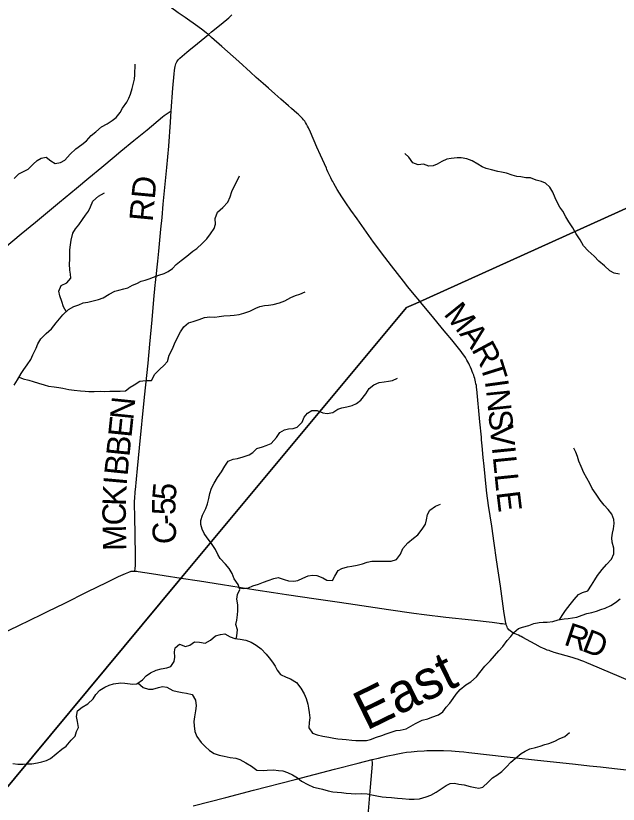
# Model space of a CAD drawing. Extents: x 1442749 to 1756758, y 235267 to 677782.
# Drawn here: x 1584563 to 1592266, y 484946 to 495025 of the extents above; entities that cross this region are included whole.
import ezdxf

# ---------------------------------------------------------------- set-up
doc = ezdxf.new("R2010")
doc.units = 0
for name, color, linetype in [('GM_X_County_Road', 7, 'Continuous'), ('GM_X_County_Road_Text', 7, 'Continuous'), ('GM_X_Minor_River', 7, 'Continuous'), ('GM_X_Minor_River_Text', 7, 'Continuous'), ('GM_X_State_Route', 7, 'Continuous'), ('GM_X_Township', 7, 'Continuous'), ('GM_X_Township_Road', 7, 'Continuous')]:
    doc.layers.add(name, color=color, linetype=linetype)

msp = doc.modelspace()

# ---------------------------------------------------------------- linework, layer by layer
at = {"layer": 'GM_X_County_Road'}
for points in [[(1587025, 494785), (1587002, 494804), (1586955, 494841), (1586889, 494889), (1586728, 495002), (1586640, 495064), (1586424, 495219), (1585934, 495567), (1585838, 495636), (1585718, 495722), (1585571, 495826), (1585546, 495843), (1585522, 495859), (1585489, 495879), (1585469, 495890), (1585449, 495901), (1585419, 495916), (1585390, 495931), (1585249, 495999), (1584874, 496173), (1584761, 496227), (1584597, 496302), (1584467, 496364)], [(1587025, 494785), (1587065, 494818), (1587188, 494917), (1587287, 494998), (1587301, 495011), (1587314, 495023), (1587324, 495035)], [(1586551, 493810), (1586572, 494098), (1586587, 494281), (1586591, 494327), (1586595, 494356), (1586599, 494376), (1586603, 494393), (1586610, 494411), (1586617, 494426), (1586624, 494437), (1586632, 494450), (1586640, 494460), (1586649, 494471), (1586662, 494484), (1586689, 494508), (1586749, 494558), (1586777, 494580), (1586886, 494670), (1587025, 494785)], [(1589707, 491401), (1589680, 491435), (1589578, 491559), (1589519, 491634), (1589365, 491830), (1589281, 491940), (1589138, 492132), (1588926, 492428), (1588846, 492540), (1588782, 492632), (1588732, 492709), (1588673, 492804), (1588628, 492881), (1588615, 492905), (1588605, 492924), (1588590, 492954), (1588579, 492977), (1588565, 493006), (1588554, 493032), (1588542, 493058), (1588534, 493076), (1588461, 493241), (1588413, 493345), (1588331, 493535), (1588305, 493592), (1588293, 493614), (1588281, 493638), (1588268, 493659), (1588257, 493676), (1588242, 493694), (1588228, 493711), (1588211, 493728), (1588196, 493744), (1588176, 493763), (1588156, 493782), (1588089, 493840), (1588052, 493873), (1587954, 493959), (1587877, 494027), (1587794, 494101), (1587724, 494161), (1587638, 494237), (1587564, 494302), (1587414, 494439), (1587196, 494634), (1587066, 494749), (1587025, 494785)], [(1586087, 487927), (1586090, 487960), (1586093, 487996), (1586094, 488019), (1586094, 488039), (1586093, 488131), (1586084, 488633), (1586081, 488767), (1586082, 488797), (1586082, 488826), (1586084, 488854), (1586085, 488878), (1586088, 488914), (1586090, 488942), (1586092, 488966), (1586119, 489237), (1586145, 489502), (1586210, 490151), (1586256, 490585), (1586278, 490826), (1586306, 491137), (1586329, 491398), (1586347, 491580), (1586350, 491616), (1586354, 491652), (1586381, 491890), (1586394, 492017), (1586419, 492295), (1586433, 492445), (1586449, 492615), (1586466, 492787), (1586494, 493085), (1586518, 493359), (1586540, 493663), (1586551, 493810)], [(1590833, 487249), (1590830, 487261), (1590822, 487306), (1590804, 487413), (1590759, 487732), (1590711, 488069), (1590681, 488284), (1590648, 488500), (1590608, 488763), (1590587, 488922), (1590578, 489004), (1590552, 489268), (1590541, 489379), (1590526, 489529), (1590519, 489606), (1590516, 489639), (1590496, 489836), (1590458, 490251), (1590455, 490274), (1590452, 490297), (1590447, 490321), (1590442, 490345), (1590436, 490367), (1590431, 490389), (1590424, 490410), (1590418, 490429), (1590408, 490457), (1590400, 490478), (1590390, 490503), (1590377, 490532), (1590366, 490557), (1590355, 490580), (1590343, 490602), (1590332, 490623), (1590312, 490656), (1590292, 490686), (1590276, 490707), (1590257, 490732), (1590240, 490754), (1590222, 490777), (1590137, 490881), (1590065, 490967), (1590018, 491025), (1589891, 491179), (1589761, 491337), (1589707, 491401)], [(1584039, 486968), (1584145, 487016), (1584338, 487106), (1584584, 487224), (1584761, 487309), (1584882, 487368), (1584979, 487416), (1585180, 487513), (1585486, 487664), (1585722, 487779), (1585878, 487856), (1585964, 487896), (1586007, 487914), (1586018, 487918), (1586029, 487921), (1586039, 487924), (1586052, 487926), (1586069, 487927), (1586087, 487927)], [(1586087, 487927), (1586099, 487926), (1586112, 487925), (1586127, 487923), (1586300, 487895), (1586459, 487869), (1586676, 487837)], [(1586676, 487837), (1586913, 487800), (1587205, 487754), (1587633, 487688), (1587860, 487654), (1588025, 487628), (1588404, 487571), (1588583, 487546), (1588703, 487529), (1588901, 487500), (1589330, 487436), (1589654, 487389), (1589784, 487373), (1590060, 487339), (1590390, 487302), (1590654, 487272), (1590742, 487261), (1590763, 487258), (1590786, 487255), (1590833, 487249)], [(1592417, 486521), (1591916, 486734), (1591865, 486755), (1591828, 486770), (1591786, 486785), (1591757, 486796), (1591717, 486808), (1591676, 486821), (1591446, 486887), (1591424, 486894), (1591402, 486902), (1591382, 486909), (1591359, 486917), (1591333, 486928), (1591304, 486940), (1591282, 486951), (1591257, 486963), (1591251, 486966), (1591150, 487021), (1591047, 487077), (1591027, 487088), (1591012, 487095), (1590991, 487105), (1590970, 487114), (1590948, 487123), (1590934, 487130), (1590920, 487137), (1590900, 487149), (1590884, 487161), (1590869, 487174), (1590858, 487187), (1590851, 487198), (1590844, 487213), (1590840, 487222), (1590837, 487232), (1590834, 487246), (1590833, 487249)]]:
    msp.add_lwpolyline(points, dxfattribs=at)
at = {"layer": 'GM_X_Minor_River'}
for points in [[(1584541, 492943), (1584602, 493003), (1584653, 493030), (1584721, 493063), (1584784, 493126), (1584835, 493174), (1584887, 493203), (1584950, 493216), (1585011, 493172), (1585067, 493137), (1585135, 493148), (1585190, 493179), (1585257, 493255), (1585330, 493326), (1585407, 493379), (1585468, 493428), (1585525, 493494), (1585586, 493543), (1585657, 493604), (1585730, 493645), (1585796, 493687), (1585847, 493726), (1585896, 493789), (1585927, 493843), (1585982, 493919), (1586009, 493970), (1586028, 494024), (1586049, 494094), (1586066, 494162), (1586082, 494214), (1586087, 494268), (1586089, 494408)], [(1592284, 491721), (1592214, 491733), (1592160, 491764), (1592089, 491827), (1592019, 491886), (1591960, 491953), (1591883, 492018), (1591824, 492085), (1591780, 492160), (1591727, 492237), (1591686, 492314), (1591633, 492390), (1591598, 492455), (1591559, 492528), (1591521, 492578), (1591488, 492635), (1591461, 492697), (1591432, 492772), (1591392, 492832), (1591337, 492883), (1591285, 492908), (1591217, 492925), (1591145, 492952), (1591083, 492955), (1591021, 492964), (1590969, 492972), (1590909, 492989), (1590839, 493014), (1590775, 493027), (1590725, 493036), (1590645, 493055), (1590579, 493071), (1590527, 493094), (1590472, 493127), (1590398, 493170), (1590330, 493197), (1590256, 493208), (1590206, 493209), (1590128, 493200), (1590074, 493190), (1590009, 493161), (1589952, 493126), (1589900, 493108), (1589846, 493103), (1589776, 493128), (1589708, 493121), (1589640, 493146), (1589589, 493217), (1589537, 493263)], [(1585682, 491421), (1585755, 491466), (1585829, 491503), (1585880, 491517), (1585944, 491536), (1585994, 491547), (1586057, 491581), (1586111, 491604), (1586166, 491633), (1586216, 491647), (1586269, 491662), (1586323, 491685), (1586390, 491707), (1586460, 491730), (1586511, 491757), (1586565, 491795), (1586614, 491846), (1586677, 491897), (1586750, 491951), (1586825, 492016), (1586877, 492051), (1586946, 492112), (1587007, 492172), (1587054, 492237), (1587099, 492305), (1587116, 492359), (1587113, 492433), (1587142, 492513), (1587209, 492572), (1587276, 492641), (1587303, 492709), (1587326, 492777), (1587357, 492841), (1587390, 492906), (1587425, 492978)], [(1585208, 491243), (1585173, 491306), (1585150, 491372), (1585127, 491444), (1585115, 491503), (1585142, 491578), (1585215, 491610), (1585268, 491671), (1585263, 491723), (1585253, 491775), (1585248, 491852), (1585253, 491910), (1585254, 491980), (1585253, 492032), (1585264, 492096), (1585273, 492158), (1585292, 492246), (1585327, 492302), (1585369, 492353), (1585418, 492419), (1585455, 492474), (1585494, 492528), (1585517, 492584), (1585548, 492654), (1585621, 492721), (1585698, 492762)], [(1584605, 490407), (1584659, 490382), (1584729, 490367), (1584783, 490350), (1584855, 490330), (1584927, 490307), (1584983, 490290), (1585053, 490281), (1585113, 490272), (1585163, 490265), (1585243, 490248), (1585309, 490237), (1585391, 490230), (1585449, 490226), (1585499, 490223), (1585563, 490220), (1585642, 490225), (1585696, 490224), (1585766, 490228), (1585898, 490226), (1585967, 490231), (1586027, 490278), (1586078, 490308), (1586147, 490355), (1586225, 490362), (1586297, 490363), (1586342, 490443), (1586403, 490506), (1586456, 490553), (1586501, 490605), (1586526, 490687), (1586567, 490768), (1586594, 490830), (1586627, 490904), (1586667, 490984), (1586710, 491047), (1586772, 491098), (1586831, 491116), (1586909, 491141), (1586976, 491166), (1587046, 491177), (1587110, 491174), (1587163, 491182), (1587225, 491189), (1587305, 491194), (1587357, 491199), (1587420, 491208), (1587480, 491222), (1587555, 491249), (1587631, 491286), (1587682, 491307), (1587744, 491320), (1587796, 491326), (1587853, 491335), (1587933, 491356), (1588002, 491381), (1588078, 491422), (1588141, 491449), (1588195, 491467), (1588264, 491496)], [(1584540, 490302), (1584585, 490373), (1584632, 490451), (1584667, 490504), (1584710, 490564), (1584755, 490629), (1584781, 490689), (1584823, 490777), (1584846, 490831), (1584884, 490894), (1584952, 490964), (1585019, 491025), (1585078, 491100), (1585123, 491152), (1585165, 491203), (1585236, 491269), (1585305, 491310), (1585368, 491331), (1585426, 491356), (1585484, 491366), (1585551, 491379), (1585621, 491398), (1585682, 491421)], [(1587382, 487062), (1587391, 487100), (1587400, 487174), (1587378, 487244), (1587391, 487300), (1587400, 487368), (1587403, 487418), (1587404, 487496), (1587389, 487569), (1587400, 487625), (1587427, 487691), (1587405, 487755), (1587356, 487826), (1587329, 487896), (1587290, 487961), (1587244, 488014), (1587177, 488087), (1587148, 488137), (1587115, 488202), (1587067, 488281), (1587010, 488353), (1586973, 488408), (1586944, 488461), (1586930, 488521), (1586931, 488571), (1586952, 488639), (1586991, 488726), (1587014, 488786), (1587031, 488856), (1587046, 488916), (1587067, 488986), (1587098, 489052), (1587141, 489123), (1587194, 489195), (1587237, 489266), (1587278, 489330), (1587343, 489359), (1587399, 489367), (1587471, 489386), (1587546, 489413), (1587596, 489442), (1587647, 489492), (1587716, 489513), (1587766, 489530), (1587827, 489559), (1587896, 489633), (1587939, 489696), (1587997, 489732), (1588052, 489743), (1588110, 489750), (1588160, 489764), (1588223, 489831), (1588252, 489895), (1588293, 489946), (1588350, 489978), (1588418, 489977), (1588490, 489950), (1588544, 489939), (1588618, 489952), (1588681, 489997), (1588731, 490013), (1588798, 490026), (1588864, 490043), (1588920, 490068), (1588977, 490110), (1589038, 490193), (1589080, 490261), (1589142, 490306), (1589211, 490337), (1589273, 490346), (1589327, 490352), (1589378, 490361), (1589444, 490392)], [(1591514, 487304), (1591549, 487357), (1591594, 487422), (1591652, 487500), (1591701, 487565), (1591758, 487625), (1591808, 487654), (1591879, 487675), (1591924, 487747), (1591967, 487816), (1592002, 487870), (1592059, 487945), (1592116, 488011), (1592181, 488078), (1592212, 488148), (1592209, 488220), (1592188, 488296), (1592186, 488351), (1592195, 488409), (1592204, 488465), (1592213, 488533), (1592208, 488585), (1592185, 488653), (1592137, 488714), (1592086, 488767), (1592036, 488832), (1591983, 488908), (1591934, 488983), (1591905, 489046), (1591864, 489112), (1591827, 489183), (1591794, 489262), (1591764, 489332), (1591745, 489393), (1591726, 489445), (1591699, 489499)], [(1587420, 487711), (1587479, 487702), (1587537, 487713), (1587594, 487737), (1587666, 487760), (1587729, 487783), (1587791, 487804), (1587862, 487831), (1587918, 487845), (1587996, 487820), (1588050, 487801), (1588118, 487798), (1588168, 487807), (1588233, 487835), (1588303, 487864), (1588358, 487875), (1588412, 487868), (1588489, 487839), (1588541, 487812), (1588611, 487808), (1588642, 487863), (1588683, 487933), (1588734, 487958), (1588806, 487981), (1588860, 487991), (1588929, 488004), (1588995, 488021), (1589054, 488040), (1589116, 488054), (1589192, 488055), (1589250, 488052), (1589305, 488053), (1589361, 488052), (1589431, 488074), (1589484, 488143), (1589513, 488217), (1589576, 488288), (1589649, 488345), (1589704, 488391), (1589761, 488462), (1589800, 488526), (1589815, 488582), (1589826, 488650), (1589857, 488707), (1589928, 488757), (1589994, 488780)], [(1588997, 485760), (1589047, 485762), (1589098, 485773), (1589174, 485802), (1589243, 485825), (1589297, 485846), (1589364, 485866), (1589428, 485887), (1589480, 485892), (1589553, 485911), (1589613, 485945), (1589672, 485980), (1589761, 486019), (1589831, 486036), (1589884, 486057), (1589968, 486090), (1590025, 486126), (1590068, 486185), (1590113, 486239), (1590155, 486298), (1590192, 486354), (1590247, 486413), (1590316, 486471), (1590383, 486510), (1590454, 486573), (1590497, 486629), (1590562, 486710), (1590629, 486777), (1590686, 486843), (1590741, 486906), (1590790, 486964), (1590845, 487037), (1590892, 487091), (1590931, 487142), (1590990, 487194), (1591044, 487211), (1591125, 487232), (1591187, 487257), (1591255, 487270), (1591306, 487272), (1591358, 487275), (1591430, 487282), (1591499, 487301), (1591573, 487314), (1591625, 487320), (1591681, 487327), (1591738, 487338), (1591806, 487363), (1591865, 487383), (1591927, 487398), (1591987, 487415), (1592044, 487434), (1592098, 487452), (1592171, 487487), (1592230, 487524), (1592292, 487572)], [(1584527, 485467), (1584589, 485460), (1584659, 485458), (1584719, 485461), (1584770, 485464), (1584842, 485475), (1584894, 485489), (1584955, 485504), (1585007, 485531), (1585080, 485588), (1585151, 485648), (1585206, 485689), (1585273, 485764), (1585322, 485818), (1585339, 485874), (1585363, 485925), (1585354, 486002), (1585339, 486068), (1585350, 486138), (1585413, 486185), (1585482, 486229), (1585553, 486294), (1585586, 486350), (1585636, 486405), (1585703, 486444), (1585756, 486470), (1585814, 486483), (1585906, 486498), (1585957, 486495), (1586061, 486482), (1586111, 486487), (1586182, 486538), (1586232, 486586), (1586285, 486625), (1586356, 486658), (1586422, 486675), (1586495, 486690), (1586545, 486706), (1586590, 486771), (1586595, 486824), (1586594, 486892), (1586602, 486944), (1586655, 486991), (1586731, 486964), (1586789, 486979), (1586846, 487023), (1586914, 487016), (1586986, 487003), (1587053, 487044), (1587116, 487097), (1587182, 487115), (1587234, 487124), (1587306, 487085), (1587362, 487064), (1587434, 487055), (1587504, 487044), (1587572, 487019), (1587638, 486978), (1587699, 486931), (1587766, 486866), (1587804, 486816), (1587845, 486761), (1587881, 486711), (1587906, 486658), (1587947, 486604), (1588021, 486569), (1588077, 486548), (1588151, 486503), (1588208, 486428), (1588251, 486355), (1588278, 486299), (1588299, 486224), (1588305, 486174), (1588316, 486120), (1588323, 486052), (1588314, 485991), (1588309, 485921), (1588355, 485853), (1588416, 485832), (1588490, 485817), (1588564, 485804), (1588628, 485791), (1588679, 485784), (1588737, 485778), (1588789, 485773), (1588861, 485766), (1588913, 485761), (1588997, 485760)], [(1586123, 486496), (1586192, 486438), (1586260, 486417), (1586316, 486418), (1586389, 486437), (1586439, 486453), (1586493, 486444), (1586571, 486401), (1586627, 486388), (1586689, 486375), (1586747, 486365), (1586817, 486348), (1586862, 486277), (1586869, 486205), (1586862, 486141), (1586847, 486063), (1586840, 486005), (1586842, 485946), (1586851, 485874), (1586876, 485810), (1586933, 485737), (1586983, 485686), (1587040, 485631), (1587098, 485596), (1587162, 485573), (1587228, 485561), (1587304, 485544), (1587376, 485533), (1587428, 485518), (1587505, 485477), (1587575, 485432), (1587644, 485383), (1587726, 485376), (1587777, 485381), (1587859, 485384), (1587921, 485379), (1587977, 485372), (1588039, 485350), (1588101, 485321), (1588166, 485282), (1588218, 485239), (1588298, 485196), (1588369, 485163), (1588429, 485152), (1588485, 485139), (1588557, 485116), (1588615, 485106), (1588673, 485101), (1588728, 485096), (1588786, 485089), (1588850, 485085), (1588904, 485080), (1588988, 485081), (1589054, 485078), (1589114, 485067), (1589180, 485052), (1589248, 485041), (1589298, 485037), (1589366, 485032), (1589443, 485023), (1589503, 485018), (1589593, 485011), (1589655, 485010), (1589723, 485015), (1589810, 485040), (1589872, 485063), (1589939, 485099), (1589989, 485134), (1590064, 485187), (1590119, 485212), (1590173, 485216), (1590227, 485203), (1590297, 485192), (1590373, 485171), (1590435, 485158), (1590485, 485150), (1590537, 485165), (1590602, 485228), (1590657, 485284), (1590714, 485317), (1590779, 485366), (1590836, 485422), (1590895, 485485), (1590972, 485552), (1591027, 485596), (1591077, 485625), (1591136, 485652), (1591208, 485669), (1591268, 485689), (1591327, 485708), (1591377, 485721), (1591456, 485750), (1591510, 485780), (1591585, 485813), (1591644, 485864)]]:
    msp.add_lwpolyline(points, dxfattribs=at)
at = {"layer": 'GM_X_State_Route'}
msp.add_lwpolyline([(1586832, 484926), (1587248, 485033), (1587601, 485124), (1588134, 485263), (1588640, 485392), (1588941, 485470), (1589119, 485516), (1589199, 485536), (1589247, 485548), (1589298, 485560), (1589341, 485569), (1589388, 485579), (1589446, 485590), (1589514, 485602), (1589559, 485610), (1589618, 485617), (1589696, 485624), (1589785, 485630), (1589820, 485631), (1589870, 485633), (1589912, 485634), (1589956, 485634), (1590031, 485632), (1590136, 485627), (1590180, 485624), (1590231, 485620), (1590291, 485614), (1590355, 485607), (1590844, 485552), (1590962, 485539), (1591197, 485513), (1591719, 485458), (1591901, 485438), (1592041, 485422), (1592217, 485403), (1592605, 485359)], dxfattribs=at)
at = {"layer": 'GM_X_Township'}
for points in [[(1600346, 496373), (1594192, 493386), (1589677, 491347), (1589558, 491294), (1586641, 487791), (1583852, 484442), (1583514, 484036), (1582700, 483060), (1581429, 481533), (1577422, 482442), (1577047, 482527), (1571453, 483622), (1569628, 483980), (1570529, 487256), (1571154, 489524), (1571164, 489560), (1572410, 494039), (1572955, 496035), (1573762, 498986), (1574679, 502300)], [(1590479, 454965), (1590579, 456501), (1589955, 460536), (1589883, 461020), (1588851, 468025), (1588027, 473613), (1587351, 478007), (1587012, 480278), (1582429, 481309), (1581429, 481533), (1582700, 483060), (1583514, 484036), (1583852, 484442), (1586641, 487791), (1589558, 491294), (1589677, 491347), (1594192, 493386), (1600346, 496373)]]:
    msp.add_lwpolyline(points, dxfattribs=at)
at = {"layer": 'GM_X_Township_Road'}
for points in [[(1584306, 491971), (1584630, 492238), (1584813, 492388), (1585122, 492642), (1585339, 492822), (1585499, 492953), (1585663, 493089), (1585822, 493222), (1585907, 493294), (1586072, 493430), (1586241, 493569), (1586439, 493732), (1586459, 493748), (1586475, 493760), (1586486, 493768), (1586499, 493777), (1586551, 493810)], [(1589064, 484757), (1589100, 485162), (1589124, 485458), (1589125, 485470), (1589123, 485485), (1589121, 485501), (1589119, 485516)]]:
    msp.add_lwpolyline(points, dxfattribs=at)

# ---------------------------------------------------------------- texts
at = {"layer": 'GM_X_County_Road_Text'}
for s, rotation, p in [('RD', 84.5908, (1586312, 492386)), ('M', 308.7977, (1590025, 491209)), ('A', 308.1319, (1590228, 490956)), ('R', 298.2968, (1590384, 490760)), ('T', 287.4673, (1590495, 490557)), ('I', 277.8144, (1590559, 490356)), ('N', 275.952, (1590576, 490236)), ('N', 84.1499, (1586064, 489850)), ('S', 275.7399, (1590603, 489974)), ('E', 84.1487, (1586041, 489626)), ('V', 275.736, (1590623, 489773)), ('B', 84.1511, (1586016, 489381)), ('I', 275.7361, (1590650, 489510)), ('B', 84.1822, (1585991, 489136)), ('L', 275.7366, (1590662, 489387)), ('L', 275.7915, (1590684, 489164)), ('I', 84.9038, (1585980, 489014)), ('K', 87.5805, (1585969, 488754)), ('5', 85.2381, (1586605, 488821)), ('5', 90, (1586605, 488643)), ('E', 276.8806, (1590708, 488934)), ('C', 90.6596, (1585972, 488512)), ('C', 91.9792, (1586617, 488276)), ('-', 91.6083, (1586608, 488522)), ('M', 91.0811, (1585978, 488187)), ('R', 341.4342, (1591558, 486988)), ('D', 338.827, (1591788, 486911))]:
    msp.add_text(s, height=300, rotation=rotation, dxfattribs=at).set_placement(p)
at = {"layer": 'GM_X_Minor_River_Text'}
msp.add_text('East', height=500, rotation=25.9928, dxfattribs=at).set_placement((1589046, 485883))

doc.saveas('drawing.dxf')
